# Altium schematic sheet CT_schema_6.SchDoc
size 308 x 301 mm
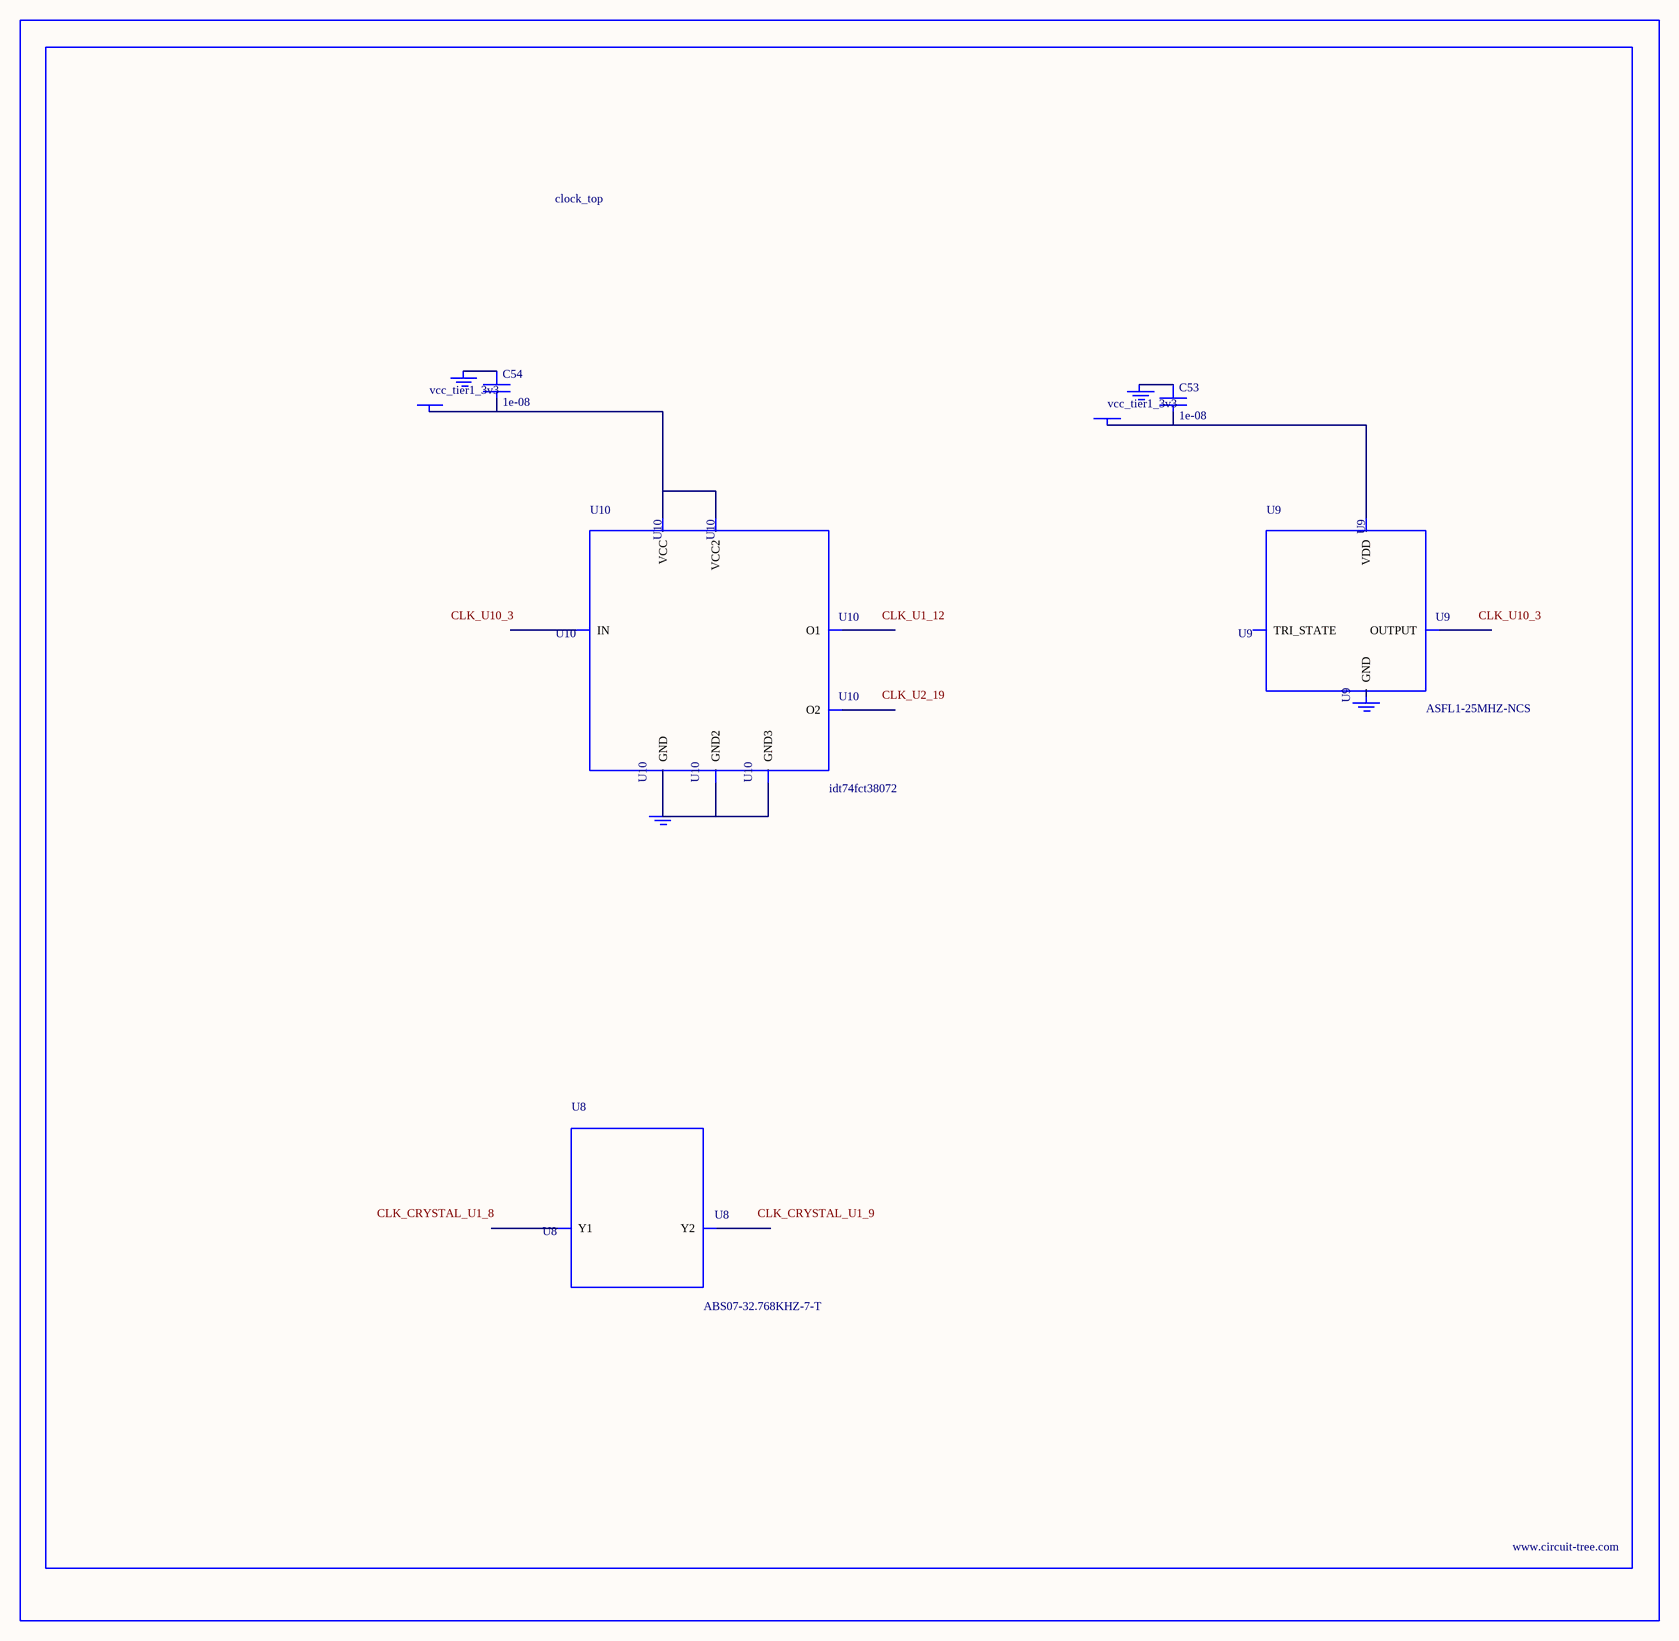
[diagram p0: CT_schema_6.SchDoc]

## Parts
BORDER5  (no value)
C53  1e-08  [C0402]
C54  1e-08  [C0402]
GND_INSTANCE_5_0  (no value)
GND_INSTANCE_5_1  (no value)
GND_INSTANCE_5_2  (no value)
GND_INSTANCE_5_3  (no value)
POWER_INSTANCE_5_0  vcc_tier1_3v3
POWER_INSTANCE_5_1  vcc_tier1_3v3
U8  ABS07-32.768KHZ-7-T  [ABS07-32.768KHZ-7-T]
U9  ASFL1-25MHZ-NCS  [ASFL1]
U10  idt74fct38072  [IDT74FCT38072]

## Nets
NetC53_1: C53.1 GND_INSTANCE_5_0.0(GND)
NetC53_2: C53.2 POWER_INSTANCE_5_0.0(PWR) U9.4(VDD)
NetC54_1: C54.1 GND_INSTANCE_5_2.0(GND)
NetC54_2: C54.2 POWER_INSTANCE_5_1.0(PWR) U10.1(VCC) U10.2(VCC2)
NetGND_INSTANCE_5_3_0: GND_INSTANCE_5_3.0(GND) U10.4(GND) U10.5(GND2) U10.8(GND3)

Not connected (* = marked no-connect by the designer): GND_INSTANCE_5_1 0(GND); U8 1(Y1) 2(Y2); U9 1(TRI_STATE) 2(GND) 3(OUTPUT); U10 3(IN) 6(O2) 7(O1)

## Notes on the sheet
- Labels drawn without touching a wire or pin: CLK_CRYSTAL_U1_8, CLK_CRYSTAL_U1_9, CLK_U1_12, CLK_U2_19, CLK_U10_3

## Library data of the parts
BORDER5 = BORDER_PAGE5
C53 C54 = C0402C103K3RAC
GND_INSTANCE_5_0-GND_INSTANCE_5_3 = GND
POWER_INSTANCE_5_0 POWER_INSTANCE_5_1 = PWR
